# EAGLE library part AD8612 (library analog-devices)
Ultrafast 4 ns Single Supply Comparators Source: http://www.analog.com/UploadedFiles/Data_Sheets/703465986AD8611_2_0.pdf Upgrade for LT1394 and LT1016 Designs
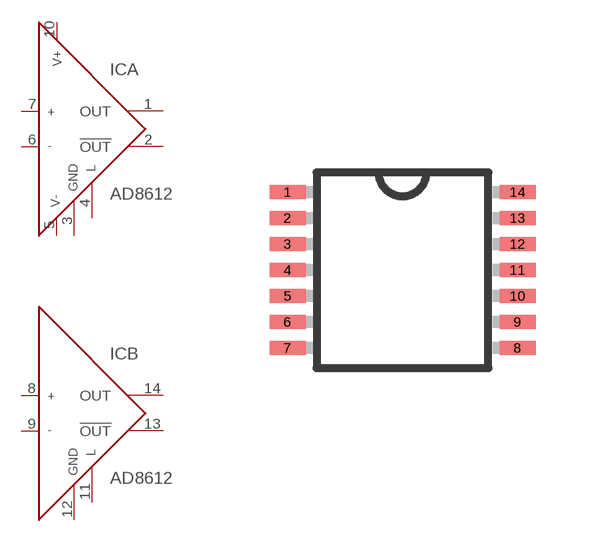
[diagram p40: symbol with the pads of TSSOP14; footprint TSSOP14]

Designator prefix IC; gates B=AD8612 A=AD8611

## AD8612RU (MF: ALTERA CORPORATION; MPN: AD8612ARUZ; OC_FARNELL: 1464996; OC_NEWARK: 88H0301)  [TSSOP14]
1  A:OUT  out
2  A:!OUT  out
3  A:GND  pwr
4  A:L  in
5  A:V-  pwr
6  A:IN-  in
7  A:IN+  in
8  B:IN+  in
9  B:IN-  in
10  A:V+  pwr
11  B:L  in
12  B:GND  pwr
13  B:!OUT  out
14  B:OUT  out

## Footprint TSSOP14 (pad centres in mm)
14-Lead Thin Shrink Small Outline Package [TSSOP] Source: Analog Devices .. 780914713ADD8704_0.pdf
smd 0.9 x 0.35: 1 -2.875,1.95; 2 -2.875,1.3; 3 -2.875,0.65; 4 -2.875,0; 5 -2.875,-0.65; 6 -2.875,-1.3; 7 -2.875,-1.95; 8 2.875,-1.95; 9 2.875,-1.3; 10 2.875,-0.65; 11 2.875,0; 12 2.875,0.65; 13 2.875,1.3; 14 2.875,1.95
